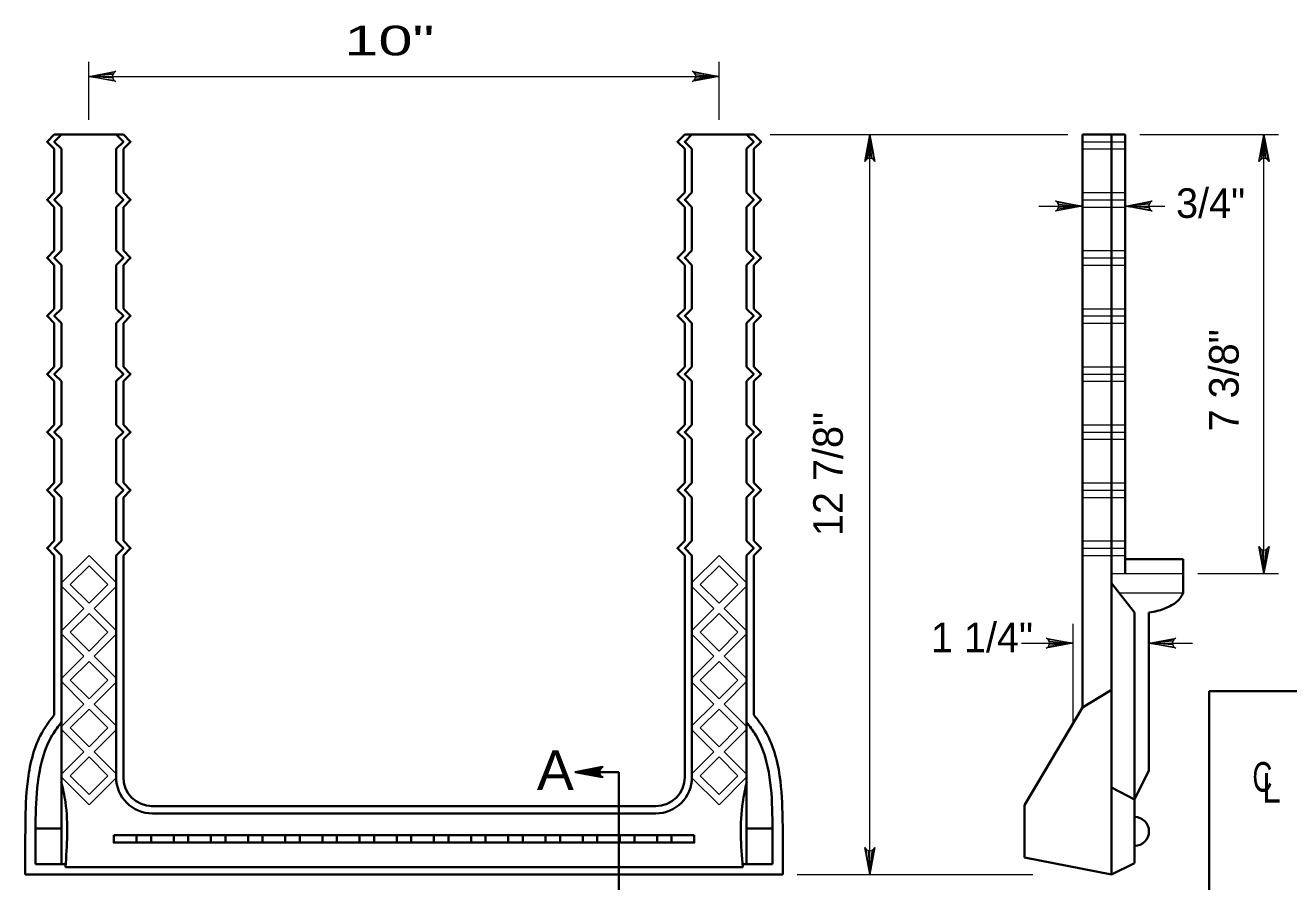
# Model space of a CAD drawing. Extents: x 15 to 140, y -57 to 117.
# Drawn here: x 19.46 to 63, y 26.34 to 55.84 of the extents above; entities that cross this region are included whole.
import ezdxf
from ezdxf.enums import TextEntityAlignment as Align

# ---------------------------------------------------------------- set-up
doc = ezdxf.new("R2010")
doc.units = 0
doc.header["$LTSCALE"] = 0.41
for name, color, linetype, lineweight in [('1', 7, 'Continuous', 35), ('10', 7, 'Continuous', 13), ('12', 7, 'Continuous', 53), ('13', 7, 'Continuous', 53), ('6', 7, 'Continuous', 13)]:
    doc.layers.add(name, color=color, linetype=linetype, lineweight=lineweight)

msp = doc.modelspace()

# ---------------------------------------------------------------- linework, layer by layer
at = {"layer": '1'}
for p, q in [((20.463, 52.0752), (22.8428, 52.0752)), ((44.5656, 52.0752), (42.1858, 52.0752)), ((55.8911, 52.0752), (55.8911, 32.3391)), ((55.8911, 52.0752), (57.3619, 52.0752)), ((56.8911, 26.5891), (56.8911, 52.0752)), ((57.3619, 36.9502), (57.3619, 52.0752)), ((20.463, 50.0752), (20.463, 51.5752)), ((20.713, 50.0752), (20.713, 51.5752)), ((22.5928, 50.0752), (22.5928, 51.5752)), ((22.8428, 50.0752), (22.8428, 51.5752)), ((42.1858, 50.0752), (42.1858, 51.5752)), ((42.4358, 50.0752), (42.4358, 51.5752)), ((44.3156, 50.0752), (44.3156, 51.5752)), ((44.5656, 50.0752), (44.5656, 51.5752)), ((20.463, 48.0752), (20.463, 49.5752)), ((20.713, 48.0752), (20.713, 49.5752)), ((22.5928, 48.0752), (22.5928, 49.5752)), ((22.8428, 48.0752), (22.8428, 49.5752)), ((42.1858, 48.0752), (42.1858, 49.5752)), ((42.4358, 48.0752), (42.4358, 49.5752)), ((44.3156, 48.0752), (44.3156, 49.5752)), ((44.5656, 48.0752), (44.5656, 49.5752)), ((20.463, 46.0752), (20.463, 47.5752)), ((20.713, 46.0752), (20.713, 47.5752)), ((22.5928, 46.0752), (22.5928, 47.5752)), ((22.8428, 46.0752), (22.8428, 47.5752)), ((42.1858, 46.0752), (42.1858, 47.5752)), ((42.4358, 46.0752), (42.4358, 47.5752)), ((44.3156, 46.0752), (44.3156, 47.5752)), ((44.5656, 46.0752), (44.5656, 47.5752)), ((20.463, 44.0752), (20.463, 45.5752)), ((20.713, 44.0752), (20.713, 45.5752)), ((22.5928, 44.0752), (22.5928, 45.5752)), ((22.8428, 44.0752), (22.8428, 45.5752)), ((42.1858, 44.0752), (42.1858, 45.5752)), ((42.4358, 44.0752), (42.4358, 45.5752)), ((44.3156, 44.0752), (44.3156, 45.5752)), ((44.5656, 44.0752), (44.5656, 45.5752)), ((20.463, 42.0752), (20.463, 43.5752)), ((20.713, 42.0752), (20.713, 43.5752)), ((22.5928, 42.0752), (22.5928, 43.5752)), ((22.8428, 42.0752), (22.8428, 43.5752)), ((42.1858, 42.0752), (42.1858, 43.5752)), ((42.4358, 42.0752), (42.4358, 43.5752)), ((44.3156, 42.0752), (44.3156, 43.5752)), ((44.5656, 42.0752), (44.5656, 43.5752)), ((20.463, 40.0752), (20.463, 41.5752)), ((20.713, 40.0752), (20.713, 41.5752)), ((22.5928, 40.0752), (22.5928, 41.5752)), ((22.8428, 40.0752), (22.8428, 41.5752)), ((42.1858, 40.0752), (42.1858, 41.5752)), ((42.4358, 40.0752), (42.4358, 41.5752)), ((44.3156, 40.0752), (44.3156, 41.5752)), ((44.5656, 40.0752), (44.5656, 41.5752)), ((20.463, 38.0752), (20.463, 39.5752)), ((20.713, 38.0752), (20.713, 39.5752)), ((22.5928, 38.0752), (22.5928, 39.5752)), ((22.8428, 38.0752), (22.8428, 39.5752)), ((42.1858, 38.0752), (42.1858, 39.5752)), ((42.4358, 38.0752), (42.4358, 39.5752)), ((44.3156, 38.0752), (44.3156, 39.5752)), ((44.5656, 38.0752), (44.5656, 39.5752)), ((20.463, 32.0891), (20.463, 37.5752)), ((20.713, 26.9391), (20.713, 37.5752)), ((22.5928, 29.9405), (22.5928, 37.5752)), ((22.8428, 29.9409), (22.8428, 37.5752)), ((42.1858, 29.9409), (42.1858, 37.5752)), ((42.4358, 29.9405), (42.4358, 37.5752)), ((44.3156, 26.9391), (44.3156, 37.5752)), ((44.5656, 32.0891), (44.5656, 37.5752)), ((57.3619, 37.4502), (59.3619, 37.4502)), ((59.3619, 36.2836), (59.3619, 37.4502)), ((56.895, 36.6168), (57.6804, 35.6169)), ((57.6804, 35.6169), (57.6804, 26.9837)), ((58.1804, 35.6169), (58.1804, 30.1676)), ((55.8911, 32.3391), (56.8587, 32.9253)), ((60.2522, 32.9068), (94.2522, 32.9068)), ((60.2522, -2.0932), (60.2522, 32.9068)), ((53.8911, 28.9759), (55.8911, 32.3391)), ((57.6804, 29.1676), (58.1804, 30.1676)), ((57.6804, 29.1676), (56.917, 29.5689)), ((23.8023, 28.9391), (41.1858, 28.9391)), ((53.8911, 27.1722), (53.8911, 28.9759)), ((23.8428, 28.6891), (41.1858, 28.6891)), ((19.8179, 28.1752), (20.713, 28.1752)), ((22.5143, 27.6884), (22.5143, 27.9384)), ((22.5143, 27.9384), (42.5143, 27.9384)), ((30.9834, 27.6884), (30.9834, 27.9384)), ((34.0452, 27.6884), (34.0452, 27.9384)), ((42.5143, 27.6884), (42.5143, 27.9384)), ((45.2107, 28.1752), (44.3156, 28.1752)), ((19.463, 26.5891), (19.463, 27.5891)), ((19.813, 26.9391), (19.813, 27.5891)), ((22.5143, 27.6884), (42.5143, 27.6884)), ((45.2156, 26.9391), (45.2156, 27.5891)), ((45.5656, 26.5891), (45.5656, 27.5891)), ((56.8911, 26.5891), (53.8911, 27.1722)), ((19.463, 26.5891), (45.5656, 26.5891)), ((19.813, 26.9391), (20.8467, 26.9391)), ((20.8462, 26.8391), (44.1824, 26.8391)), ((45.2156, 26.9391), (44.1819, 26.9391)), ((56.8911, 26.5891), (57.6804, 26.9837))]:
    msp.add_line(p, q, dxfattribs=at)
for points in [[(20.463, 52.0752), (20.213, 51.8252), (20.463, 51.5752)], [(20.713, 52.0752), (20.463, 51.8252), (20.713, 51.5752)], [(22.5928, 52.0752), (22.8428, 51.8252), (22.5928, 51.5752)], [(22.8428, 52.0752), (23.0928, 51.8252), (22.8428, 51.5752)], [(42.1858, 52.0752), (41.9358, 51.8252), (42.1858, 51.5752)], [(42.4358, 52.0752), (42.1858, 51.8252), (42.4358, 51.5752)], [(44.3156, 52.0752), (44.5656, 51.8252), (44.3156, 51.5752)], [(44.5656, 52.0752), (44.8156, 51.8252), (44.5656, 51.5752)], [(20.463, 50.0752), (20.213, 49.8252), (20.463, 49.5752)], [(20.713, 50.0752), (20.463, 49.8252), (20.713, 49.5752)], [(22.5928, 50.0752), (22.8428, 49.8252), (22.5928, 49.5752)], [(22.8428, 50.0752), (23.0928, 49.8252), (22.8428, 49.5752)], [(42.1858, 50.0752), (41.9358, 49.8252), (42.1858, 49.5752)], [(42.4358, 50.0752), (42.1858, 49.8252), (42.4358, 49.5752)], [(44.3156, 50.0752), (44.5656, 49.8252), (44.3156, 49.5752)], [(44.5656, 50.0752), (44.8156, 49.8252), (44.5656, 49.5752)], [(20.463, 48.0752), (20.213, 47.8252), (20.463, 47.5752)], [(20.713, 48.0752), (20.463, 47.8252), (20.713, 47.5752)], [(22.5928, 48.0752), (22.8428, 47.8252), (22.5928, 47.5752)], [(22.8428, 48.0752), (23.0928, 47.8252), (22.8428, 47.5752)], [(42.1858, 48.0752), (41.9358, 47.8252), (42.1858, 47.5752)], [(42.4358, 48.0752), (42.1858, 47.8252), (42.4358, 47.5752)], [(44.3156, 48.0752), (44.5656, 47.8252), (44.3156, 47.5752)], [(44.5656, 48.0752), (44.8156, 47.8252), (44.5656, 47.5752)], [(20.463, 46.0752), (20.213, 45.8252), (20.463, 45.5752)], [(20.463, 46.0752), (20.213, 45.8252), (20.463, 45.5752)], [(20.713, 46.0752), (20.463, 45.8252), (20.713, 45.5752)], [(22.5928, 46.0752), (22.8428, 45.8252), (22.5928, 45.5752)], [(22.8428, 46.0752), (23.0928, 45.8252), (22.8428, 45.5752)], [(42.1858, 46.0752), (41.9358, 45.8252), (42.1858, 45.5752)], [(42.4358, 46.0752), (42.1858, 45.8252), (42.4358, 45.5752)], [(44.3156, 46.0752), (44.5656, 45.8252), (44.3156, 45.5752)], [(44.5656, 46.0752), (44.8156, 45.8252), (44.5656, 45.5752)], [(44.5656, 46.0752), (44.8156, 45.8252), (44.5656, 45.5752)], [(20.463, 44.0752), (20.213, 43.8252), (20.463, 43.5752)], [(20.713, 44.0752), (20.463, 43.8252), (20.713, 43.5752)], [(22.5928, 44.0752), (22.8428, 43.8252), (22.5928, 43.5752)], [(22.8428, 44.0752), (23.0928, 43.8252), (22.8428, 43.5752)], [(42.1858, 44.0752), (41.9358, 43.8252), (42.1858, 43.5752)], [(42.4358, 44.0752), (42.1858, 43.8252), (42.4358, 43.5752)], [(44.3156, 44.0752), (44.5656, 43.8252), (44.3156, 43.5752)], [(44.5656, 44.0752), (44.8156, 43.8252), (44.5656, 43.5752)], [(20.463, 42.0752), (20.213, 41.8252), (20.463, 41.5752)], [(20.713, 42.0752), (20.463, 41.8252), (20.713, 41.5752)], [(22.5928, 42.0752), (22.8428, 41.8252), (22.5928, 41.5752)], [(22.8428, 42.0752), (23.0928, 41.8252), (22.8428, 41.5752)], [(42.1858, 42.0752), (41.9358, 41.8252), (42.1858, 41.5752)], [(42.4358, 42.0752), (42.1858, 41.8252), (42.4358, 41.5752)], [(44.3156, 42.0752), (44.5656, 41.8252), (44.3156, 41.5752)], [(44.5656, 42.0752), (44.8156, 41.8252), (44.5656, 41.5752)], [(20.463, 40.0752), (20.213, 39.8252), (20.463, 39.5752)], [(20.713, 40.0752), (20.463, 39.8252), (20.713, 39.5752)], [(22.5928, 40.0752), (22.8428, 39.8252), (22.5928, 39.5752)], [(22.8428, 40.0752), (23.0928, 39.8252), (22.8428, 39.5752)], [(42.1858, 40.0752), (41.9358, 39.8252), (42.1858, 39.5752)], [(42.4358, 40.0752), (42.1858, 39.8252), (42.4358, 39.5752)], [(44.3156, 40.0752), (44.5656, 39.8252), (44.3156, 39.5752)], [(44.5656, 40.0752), (44.8156, 39.8252), (44.5656, 39.5752)], [(20.463, 38.0752), (20.213, 37.8252), (20.463, 37.5752)], [(20.713, 38.0752), (20.463, 37.8252), (20.713, 37.5752)], [(22.5928, 38.0752), (22.8428, 37.8252), (22.5928, 37.5752)], [(22.8428, 38.0752), (23.0928, 37.8252), (22.8428, 37.5752)], [(42.1858, 38.0752), (41.9358, 37.8252), (42.1858, 37.5752)], [(42.4358, 38.0752), (42.1858, 37.8252), (42.4358, 37.5752)], [(44.3156, 38.0752), (44.5656, 37.8252), (44.3156, 37.5752)], [(44.5656, 38.0752), (44.8156, 37.8252), (44.5656, 37.5752)]]:
    msp.add_lwpolyline(points, dxfattribs=at)
for points in [[(22.5143, 27.9384), (23.2956, 27.9384), (23.2956, 27.6884), (22.5143, 27.6884)], [(23.7956, 27.9384), (24.5769, 27.9384), (24.5769, 27.6884), (23.7956, 27.6884)], [(25.0769, 27.9384), (25.8582, 27.9384), (25.8582, 27.6884), (25.0769, 27.6884)], [(26.3582, 27.9384), (27.1395, 27.9384), (27.1395, 27.6884), (26.3582, 27.6884)], [(27.6395, 27.9384), (28.4208, 27.9384), (28.4208, 27.6884), (27.6395, 27.6884)], [(28.9208, 27.9384), (29.7021, 27.9384), (29.7021, 27.6884), (28.9208, 27.6884)], [(30.2021, 27.9384), (30.9834, 27.9384), (30.9834, 27.6884), (30.2021, 27.6884)], [(31.4834, 27.9384), (32.2647, 27.9384), (32.2647, 27.6884), (31.4834, 27.6884)], [(33.5452, 27.9384), (32.7639, 27.9384), (32.7639, 27.6884), (33.5452, 27.6884)], [(34.8265, 27.9384), (34.0452, 27.9384), (34.0452, 27.6884), (34.8265, 27.6884)], [(36.1078, 27.9384), (35.3265, 27.9384), (35.3265, 27.6884), (36.1078, 27.6884)], [(37.3891, 27.9384), (36.6078, 27.9384), (36.6078, 27.6884), (37.3891, 27.6884)], [(38.6704, 27.9384), (37.8891, 27.9384), (37.8891, 27.6884), (38.6704, 27.6884)], [(39.9517, 27.9384), (39.1704, 27.9384), (39.1704, 27.6884), (39.9517, 27.6884)], [(41.233, 27.9384), (40.4517, 27.9384), (40.4517, 27.6884), (41.233, 27.6884)], [(42.5143, 27.9384), (41.733, 27.9384), (41.733, 27.6884), (42.5143, 27.6884)]]:
    msp.add_lwpolyline(points, close=True, dxfattribs=at)
for centre, radius, start, end in [((23.8428, 29.9405), 1.25, 180, 270), ((23.8428, 29.9409), 1, 180, 270), ((41.1858, 29.9409), 1, 270, 0), ((41.1858, 29.9405), 1.25, 270, 0), ((57.6822, 28.0723), 0.5, 270, 90)]:
    msp.add_arc(centre, radius, start, end, dxfattribs=at)
for points in [[(59.3619, 36.2836), (59.2455, 36.0915), (58.9062, 35.8329), (58.4701, 35.6632), (58.1804, 35.6169)], [(19.463, 27.5891), (19.4707, 28.5145), (19.572, 29.9921), (20.0788, 31.5422), (20.463, 32.0891)], [(19.813, 27.5862), (19.8206, 28.501), (19.9182, 29.9247), (20.3952, 31.3838), (20.713, 31.8361)], [(45.2156, 27.5862), (45.208, 28.501), (45.1104, 29.9247), (44.6334, 31.3838), (44.3156, 31.8361)], [(45.5656, 27.5891), (45.5579, 28.5145), (45.4566, 29.9921), (44.9498, 31.5422), (44.5656, 32.0891)], [(20.7056, 29.7791), (20.8462, 29.0756), (20.8462, 26.8386)], [(44.323, 29.7791), (44.1824, 29.0756), (44.1824, 26.8386)]]:
    msp.add_spline(points, degree=3, dxfattribs=at)
at = {"layer": '10'}
for p, q in [((21.6529, 52.5752), (21.6529, 54.5752)), ((43.3757, 52.5752), (43.3757, 54.5752)), ((21.6529, 54.0752), (43.3757, 54.0752)), ((45.1329, 52.0752), (55.3911, 52.0752)), ((48.5656, 26.5891), (48.5656, 52.0752)), ((57.8619, 52.0752), (62.6447, 52.0752)), ((62.1447, 36.9502), (62.1447, 52.0752)), ((54.3911, 49.6101), (55.8911, 49.6101)), ((57.3619, 49.6101), (58.7325, 49.6101)), ((59.8619, 36.9502), (62.6447, 36.9502)), ((55.569, 31.7975), (55.569, 35.2263)), ((53.7911, 34.5566), (55.569, 34.5566)), ((58.1804, 34.5566), (59.6804, 34.5566)), ((46.0656, 26.5891), (54.1854, 26.5891))]:
    msp.add_line(p, q, dxfattribs=at)
at = {"layer": '10', "lineweight": 35}
for p, q in [((38.4208, 30.1165), (39.9208, 30.1165)), ((39.9208, 30.1165), (39.9208, 25.1165))]:
    msp.add_line(p, q, dxfattribs=at)
at = {"layer": '10'}
for points in [[(21.6529, 54.0752), (22.585, 54.25), (22.5132, 54.2002), (22.4761, 54.1377), (22.4654, 54.0752), (22.4761, 54.0127), (22.5132, 53.9502), (22.585, 53.9005), (21.6529, 54.0752), (22.5132, 53.9502), (22.4761, 54.0127), (21.6529, 54.0752), (22.4654, 54.0752), (22.4761, 54.1377), (21.6529, 54.0752), (22.5132, 54.2002)], [(43.3757, 54.0752), (42.4436, 53.9005), (42.5154, 53.9502), (42.5525, 54.0127), (42.5632, 54.0752), (42.5525, 54.1377), (42.5154, 54.2002), (42.4436, 54.25), (43.3757, 54.0752), (42.5154, 54.2002), (42.5525, 54.1377), (43.3757, 54.0752), (42.5632, 54.0752), (42.5525, 54.0127), (43.3757, 54.0752), (42.5154, 53.9502)], [(48.5656, 52.0752), (48.7404, 51.1431), (48.6906, 51.215), (48.6281, 51.252), (48.5656, 51.2627), (48.5031, 51.252), (48.4406, 51.215), (48.3908, 51.1431), (48.5656, 52.0752), (48.4406, 51.215), (48.5031, 51.252), (48.5656, 52.0752), (48.5656, 51.2627), (48.6281, 51.252), (48.5656, 52.0752), (48.6906, 51.215)], [(62.1447, 52.0752), (62.3195, 51.1431), (62.2697, 51.215), (62.2072, 51.252), (62.1447, 51.2627), (62.0822, 51.252), (62.0197, 51.215), (61.97, 51.1431), (62.1447, 52.0752), (62.0197, 51.215), (62.0822, 51.252), (62.1447, 52.0752), (62.1447, 51.2627), (62.2072, 51.252), (62.1447, 52.0752), (62.2697, 51.215)], [(55.8911, 49.6101), (54.959, 49.4354), (55.0309, 49.4851), (55.0679, 49.5476), (55.0786, 49.6101), (55.0679, 49.6726), (55.0309, 49.7351), (54.959, 49.7849), (55.8911, 49.6101), (55.0309, 49.7351), (55.0679, 49.6726), (55.8911, 49.6101), (55.0786, 49.6101), (55.0679, 49.5476), (55.8911, 49.6101), (55.0309, 49.4851)], [(57.3619, 49.6101), (58.294, 49.7849), (58.2222, 49.7351), (58.1852, 49.6726), (58.1744, 49.6101), (58.1852, 49.5476), (58.2222, 49.4851), (58.294, 49.4354), (57.3619, 49.6101), (58.2222, 49.4851), (58.1852, 49.5476), (57.3619, 49.6101), (58.1744, 49.6101), (58.1852, 49.6726), (57.3619, 49.6101), (58.2222, 49.7351)], [(62.1447, 36.9502), (61.97, 37.8823), (62.0197, 37.8105), (62.0822, 37.7734), (62.1447, 37.7627), (62.2072, 37.7734), (62.2697, 37.8105), (62.3195, 37.8823), (62.1447, 36.9502), (62.2697, 37.8105), (62.2072, 37.7734), (62.1447, 36.9502), (62.1447, 37.7627), (62.0822, 37.7734), (62.1447, 36.9502), (62.0197, 37.8105)], [(55.569, 34.5566), (54.637, 34.3819), (54.7088, 34.4316), (54.7458, 34.4941), (54.7565, 34.5566), (54.7458, 34.6191), (54.7088, 34.6816), (54.637, 34.7314), (55.569, 34.5566), (54.7088, 34.6816), (54.7458, 34.6191), (55.569, 34.5566), (54.7565, 34.5566), (54.7458, 34.4941), (55.569, 34.5566), (54.7088, 34.4316)], [(58.1804, 34.5566), (59.1125, 34.7314), (59.0406, 34.6816), (59.0036, 34.6191), (58.9929, 34.5566), (59.0036, 34.4941), (59.0406, 34.4316), (59.1125, 34.3819), (58.1804, 34.5566), (59.0406, 34.4316), (59.0036, 34.4941), (58.1804, 34.5566), (58.9929, 34.5566), (59.0036, 34.6191), (58.1804, 34.5566), (59.0406, 34.6816)], [(48.5656, 26.5891), (48.3908, 27.5211), (48.4406, 27.4493), (48.5031, 27.4123), (48.5656, 27.4016), (48.6281, 27.4123), (48.6906, 27.4493), (48.7404, 27.5211), (48.5656, 26.5891), (48.6906, 27.4493), (48.6281, 27.4123), (48.5656, 26.5891), (48.5656, 27.4016), (48.5031, 27.4123), (48.5656, 26.5891), (48.4406, 27.4493)]]:
    msp.add_lwpolyline(points, dxfattribs=at)
at = {"layer": '10', "lineweight": 35}
msp.add_lwpolyline([(38.4208, 30.1165), (39.3529, 30.2912), (39.281, 30.2415), (39.244, 30.179), (39.2333, 30.1165), (39.244, 30.054), (39.281, 29.9915), (39.3529, 29.9417), (38.4208, 30.1165), (39.281, 29.9915), (39.244, 30.054), (38.4208, 30.1165), (39.2333, 30.1165), (39.244, 30.179), (38.4208, 30.1165), (39.281, 30.2415)], dxfattribs=at)
at = {"layer": '6'}
for p, q in [((55.8911, 51.8252), (57.3619, 51.8252)), ((55.8911, 51.5752), (57.3619, 51.5752)), ((55.8911, 50.0752), (57.3619, 50.0752)), ((55.8911, 49.8252), (57.3619, 49.8252)), ((55.8911, 49.5752), (57.3619, 49.5752)), ((55.8911, 48.0752), (57.3619, 48.0752)), ((55.8911, 47.8252), (57.3619, 47.8252)), ((55.8911, 47.5752), (57.3619, 47.5752)), ((55.8911, 46.0752), (57.3619, 46.0752)), ((55.8911, 45.8252), (57.3619, 45.8252)), ((55.8911, 45.5752), (57.3619, 45.5752)), ((55.8911, 44.0752), (57.3619, 44.0752)), ((55.8911, 43.8252), (57.3619, 43.8252)), ((55.8911, 43.5752), (57.3619, 43.5752)), ((55.8911, 42.0752), (57.3619, 42.0752)), ((55.8911, 41.8252), (57.3619, 41.8252)), ((55.8911, 41.5752), (57.3619, 41.5752)), ((55.8911, 40.0752), (57.3619, 40.0752)), ((55.8911, 39.8252), (57.3619, 39.8252)), ((55.8911, 39.5752), (57.3619, 39.5752)), ((55.8911, 38.0752), (57.3619, 38.0752)), ((55.8911, 37.8252), (57.3619, 37.8252)), ((55.8911, 37.5752), (57.3619, 37.5752)), ((56.8911, 36.9502), (59.3619, 36.9502)), ((20.713, 36.522), (21.483, 35.752)), ((21.8366, 35.752), (22.5928, 36.5082)), ((43.192, 35.752), (42.4358, 36.5082)), ((44.3156, 36.522), (43.5456, 35.752)), ((57.1568, 36.2836), (59.3619, 36.2836)), ((21.483, 35.752), (20.713, 34.982)), ((22.5928, 34.9957), (21.8366, 35.752)), ((42.4358, 34.9957), (43.192, 35.752)), ((43.5456, 35.752), (44.3156, 34.982)), ((21.0133, 34.9288), (21.6598, 35.5752)), ((21.6598, 35.5752), (22.3062, 34.9288)), ((43.3688, 35.5752), (42.7224, 34.9288)), ((44.0153, 34.9288), (43.3688, 35.5752)), ((21.483, 34.1056), (20.713, 34.8755)), ((22.5928, 34.8618), (21.8365, 34.1056)), ((42.4358, 34.8618), (43.1921, 34.1056)), ((43.5456, 34.1056), (44.3156, 34.8755)), ((21.483, 34.1056), (20.713, 33.3356)), ((22.5928, 33.3493), (21.8365, 34.1056)), ((42.4358, 33.3493), (43.1921, 34.1056)), ((43.5456, 34.1056), (44.3156, 33.3356)), ((21.6598, 33.9288), (21.0133, 33.2823)), ((22.3062, 33.2823), (21.6598, 33.9288)), ((42.7224, 33.2823), (43.3688, 33.9288)), ((43.3688, 33.9288), (44.0153, 33.2823)), ((21.483, 32.4591), (20.713, 33.2291)), ((21.6598, 32.6359), (21.0133, 33.2823)), ((22.3062, 33.2823), (21.6598, 32.6359)), ((22.5928, 33.2154), (21.8365, 32.4591)), ((42.4358, 33.2154), (43.1921, 32.4591)), ((42.7224, 33.2823), (43.3688, 32.6359)), ((43.3688, 32.6359), (44.0153, 33.2823)), ((43.5456, 32.4591), (44.3156, 33.2291)), ((21.483, 32.4591), (20.713, 31.6891)), ((21.6598, 32.2823), (21.0133, 31.6359)), ((22.3062, 31.6359), (21.6598, 32.2823)), ((22.5928, 31.7028), (21.8365, 32.4591)), ((42.4358, 31.7028), (43.1921, 32.4591)), ((42.7224, 31.6359), (43.3688, 32.2823)), ((43.3688, 32.2823), (44.0153, 31.6359)), ((43.5456, 32.4591), (44.3156, 31.6891)), ((21.483, 30.8127), (20.713, 31.5826)), ((21.6597, 30.9894), (21.0133, 31.6359)), ((22.3062, 31.6359), (21.6597, 30.9894)), ((22.5928, 31.569), (21.8365, 30.8127)), ((42.4358, 31.569), (43.1921, 30.8127)), ((42.7224, 31.6359), (43.3689, 30.9894)), ((43.3689, 30.9894), (44.0153, 31.6359)), ((43.5456, 30.8127), (44.3156, 31.5826)), ((21.483, 30.8127), (20.713, 30.0427)), ((21.6597, 30.6359), (21.0133, 29.9894)), ((22.3062, 29.9894), (21.6597, 30.6359)), ((22.5928, 30.0564), (21.8365, 30.8127)), ((42.4358, 30.0564), (43.1921, 30.8127)), ((42.7224, 29.9894), (43.3689, 30.6359)), ((43.3689, 30.6359), (44.0153, 29.9894)), ((43.5456, 30.8127), (44.3156, 30.0427)), ((21.6597, 28.9894), (20.713, 29.9362)), ((22.5928, 29.9225), (21.6597, 28.9894)), ((42.4358, 29.9225), (43.3689, 28.9894)), ((43.3689, 28.9894), (44.3156, 29.9362))]:
    msp.add_line(p, q, dxfattribs=at)
for points in [[(20.713, 36.6284), (21.6598, 37.5752), (22.5928, 36.6422)], [(44.3156, 36.6284), (43.3688, 37.5752), (42.4358, 36.6422)], [(22.3062, 34.9288), (21.6598, 34.2823), (21.0133, 34.9288)], [(42.7224, 34.9288), (43.3688, 34.2823), (44.0153, 34.9288)], [(22.3062, 29.9894), (21.6597, 29.343), (21.0133, 29.9894)], [(42.7224, 29.9894), (43.3689, 29.343), (44.0153, 29.9894)]]:
    msp.add_lwpolyline(points, dxfattribs=at)
for points in [[(21.6598, 35.9288), (21.0133, 36.5752), (21.6598, 37.2217), (22.3062, 36.5752)], [(43.3688, 35.9288), (44.0153, 36.5752), (43.3688, 37.2217), (42.7224, 36.5752)]]:
    msp.add_lwpolyline(points, close=True, dxfattribs=at)

# ---------------------------------------------------------------- texts
at = {"layer": '12', "width": 1.05}
msp.add_text('A', height=1.36, dxfattribs=at).set_placement((37.7267, 29.499), align=Align.CENTER)
at = {"layer": '12'}
for s, width, p in [('C', 0.7, (61.7456, 29.4396)), ('L', 0.85, (62.0822, 29.0605))]:
    msp.add_text(s, height=1.02, dxfattribs=dict(at, width=width)).set_placement(p)
at = {"layer": '13', "width": 1.55}
msp.add_text('10"', height=1.02, dxfattribs=at).set_placement((32.0068, 54.8002), align=Align.CENTER)
at = {"layer": '13'}
for s, p in [('3/4"', (60.3055, 49.2009)), ('1 1/4"', (52.4285, 34.2438))]:
    msp.add_text(s, height=1.02, dxfattribs=at).set_placement(p, align=Align.CENTER)
for s, p in [('7 3/8"', (61.2735, 43.6072)), ('12 7/8"', (47.6324, 40.3802))]:
    msp.add_text(s, height=1.02, rotation=90, dxfattribs=at).set_placement(p, align=Align.CENTER)

doc.saveas('drawing.dxf')
